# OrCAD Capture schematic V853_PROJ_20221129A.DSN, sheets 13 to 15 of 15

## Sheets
13 12 CARD/USB: size A3; note: USB
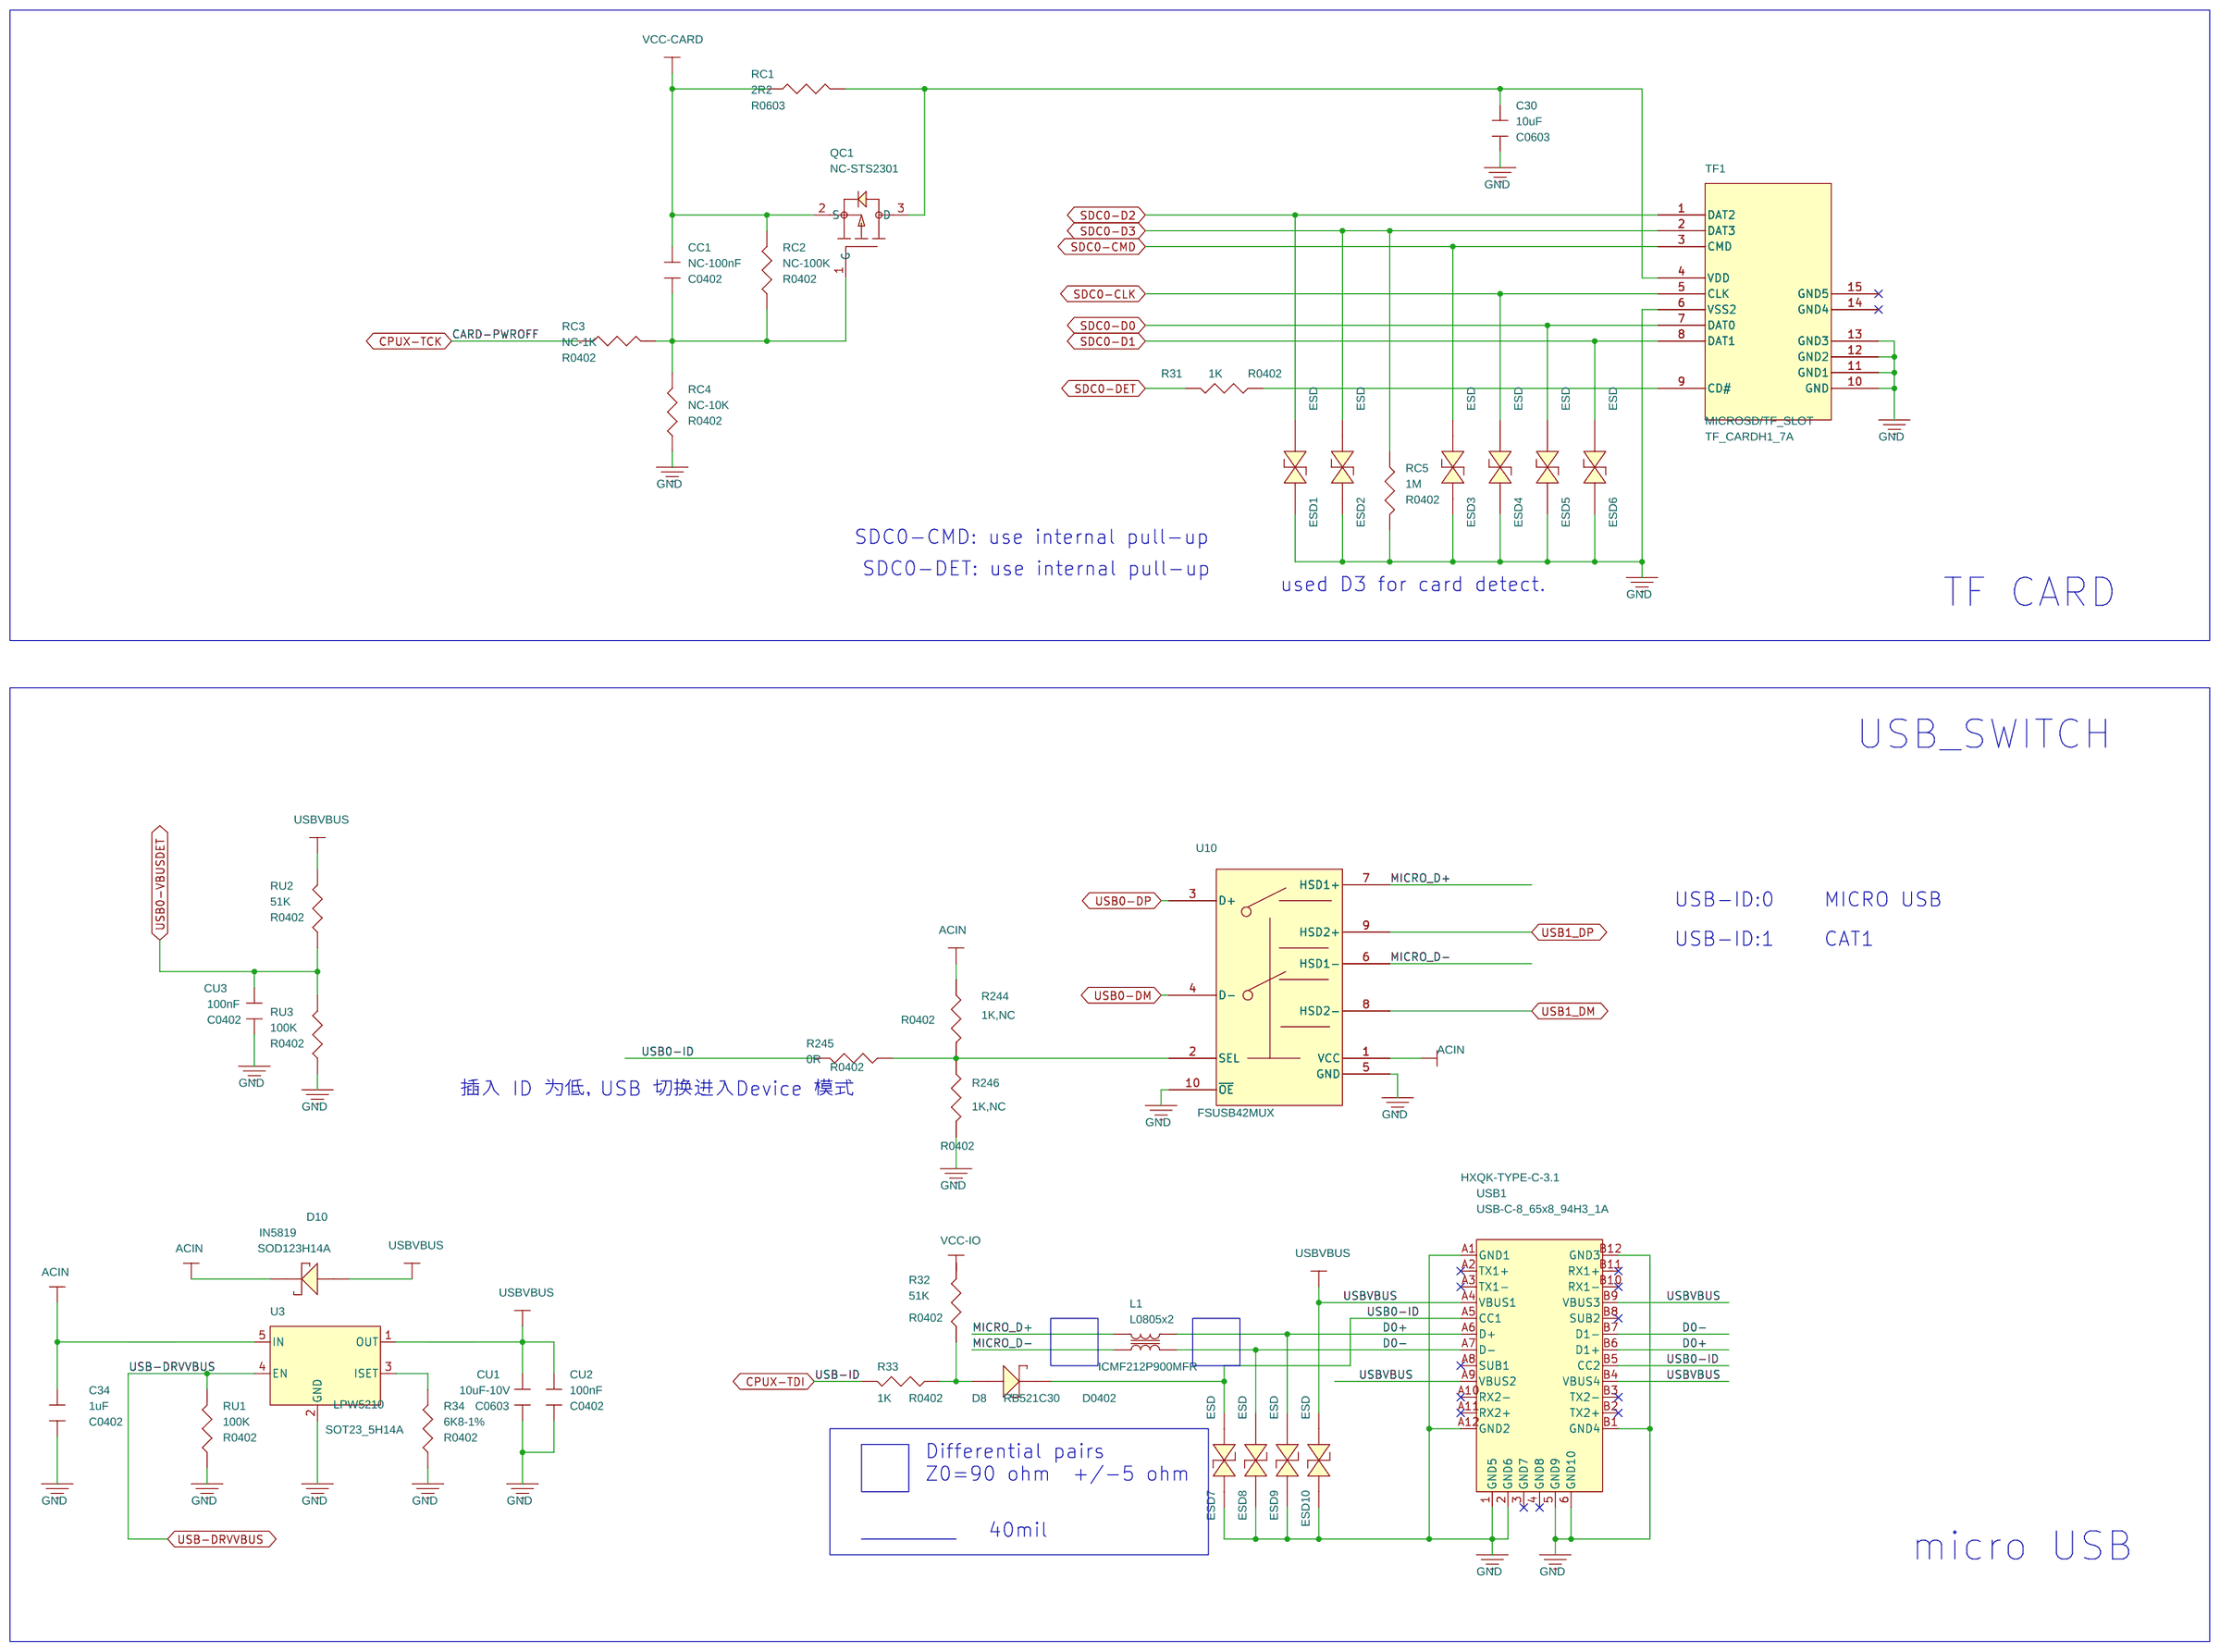
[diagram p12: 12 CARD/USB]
14 07 JTAG/DEBUG: size A3; note: JTAG/DEBUG
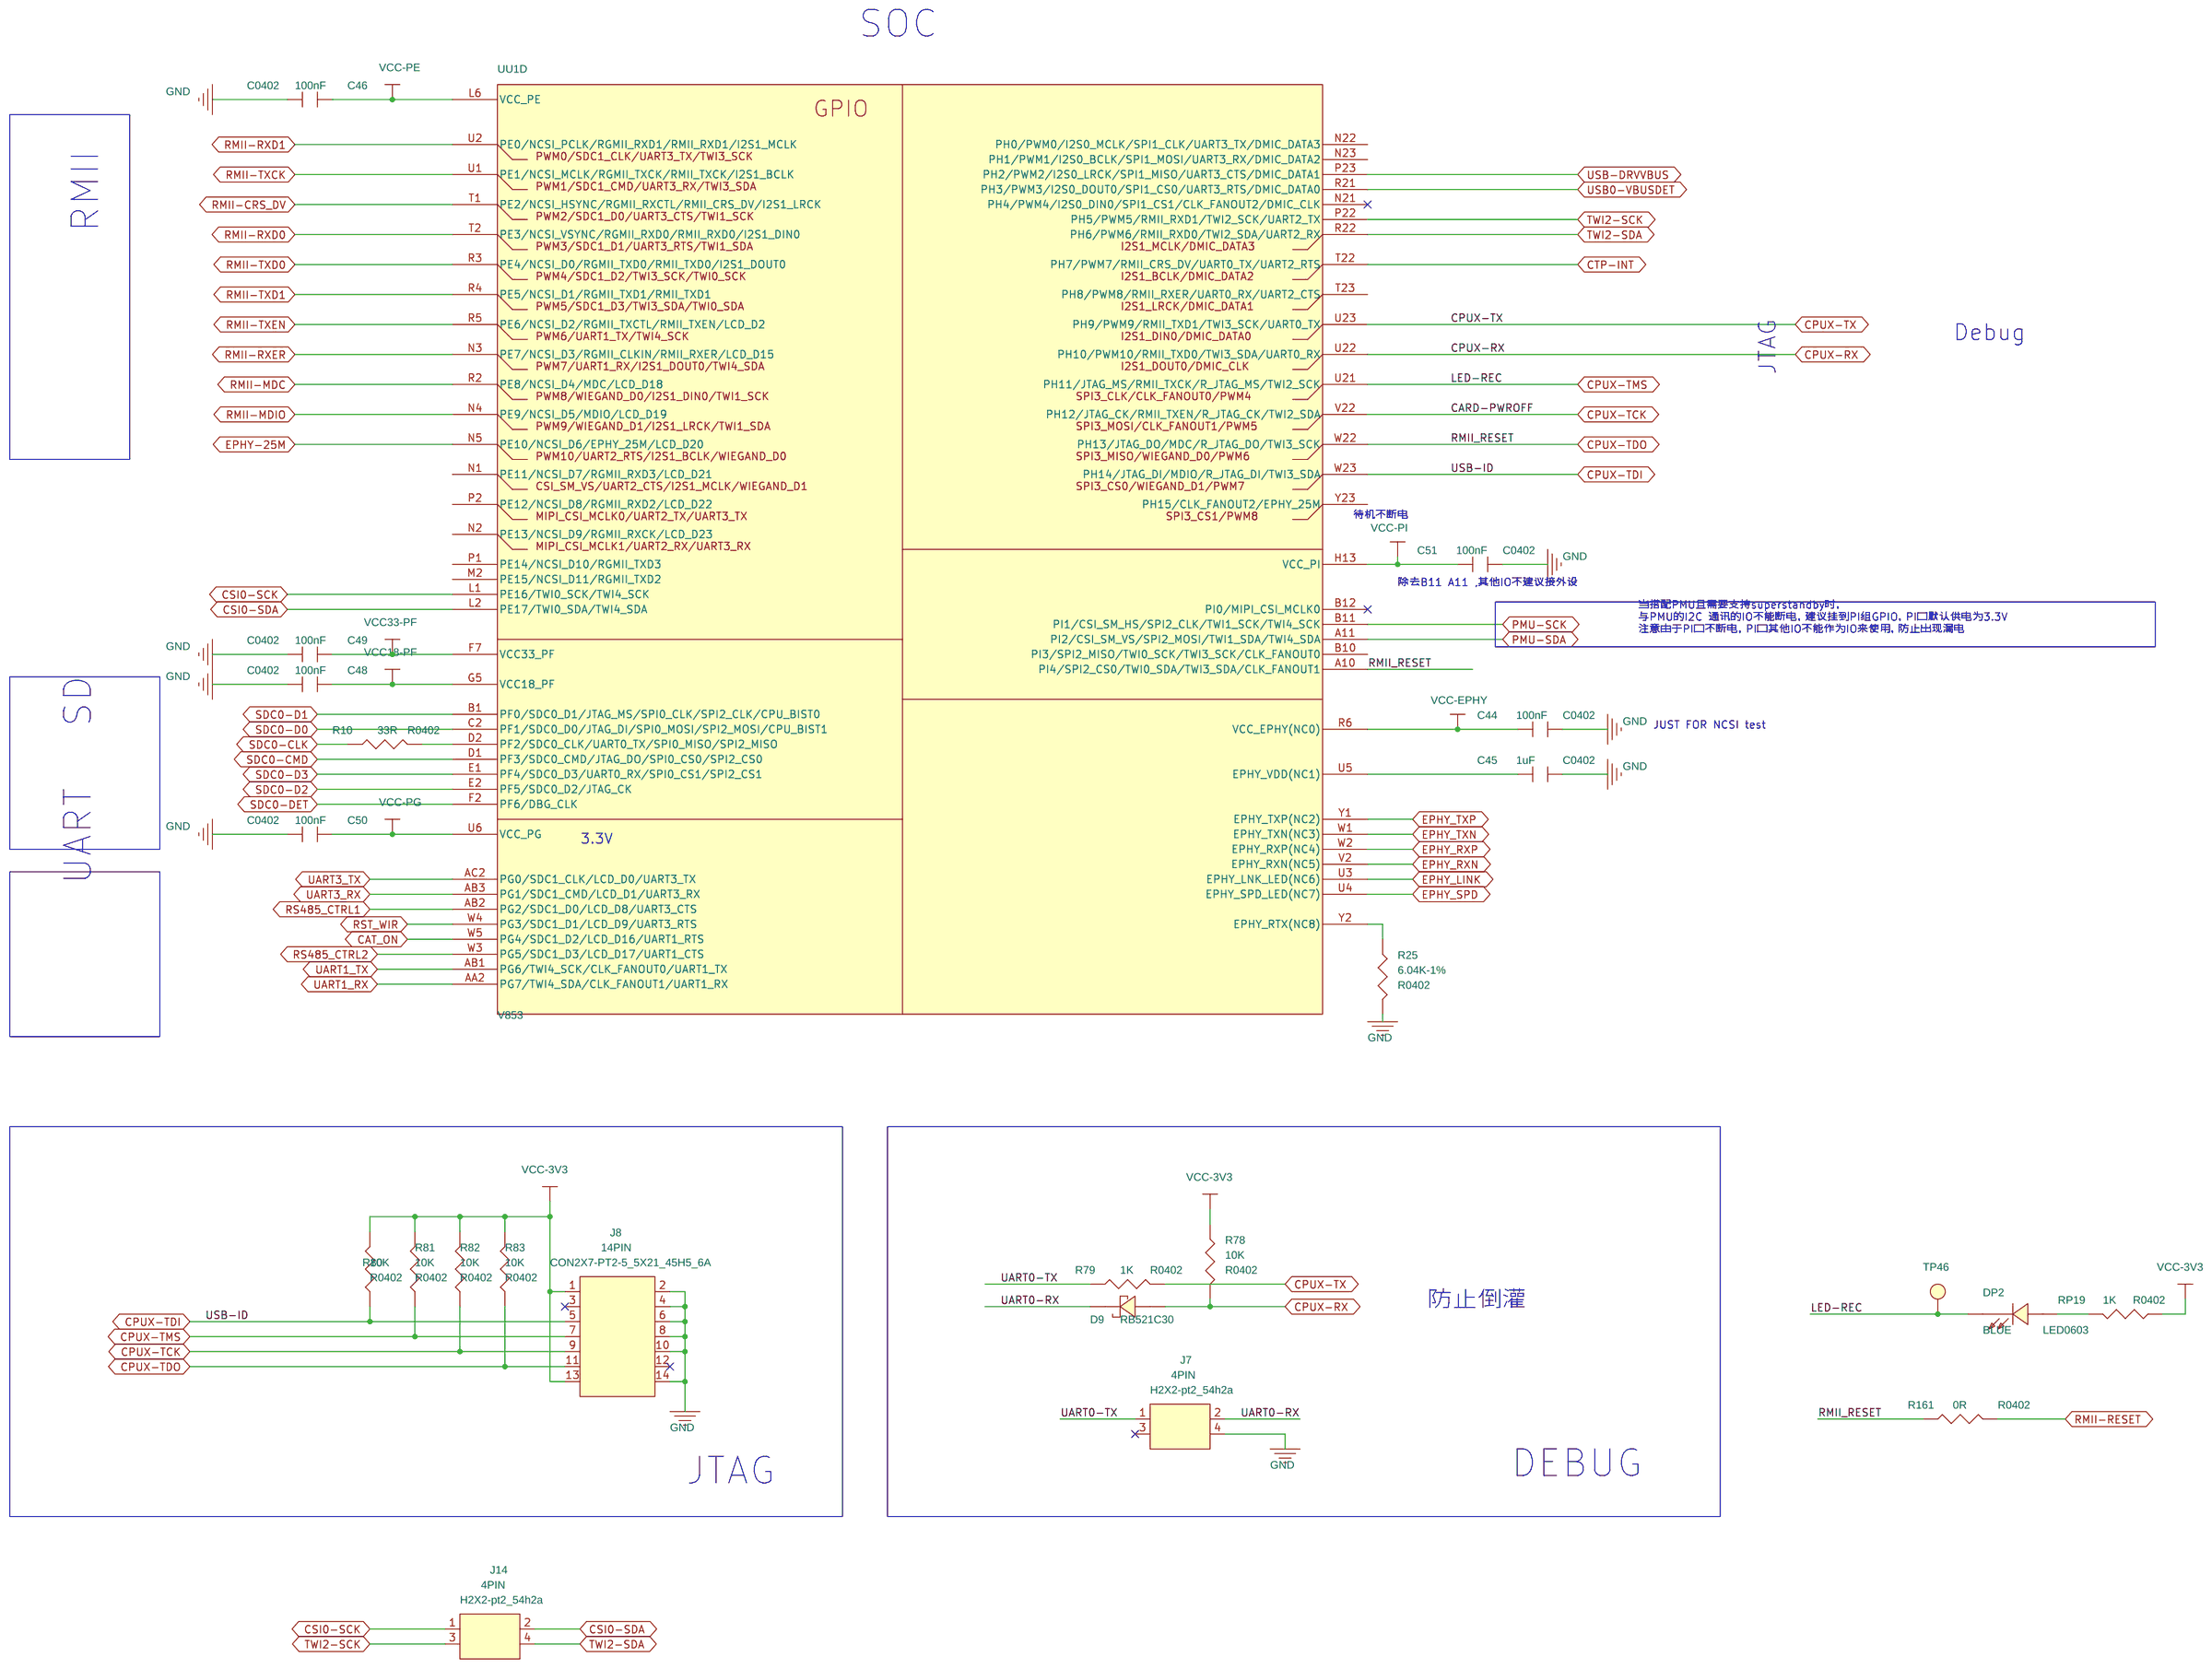
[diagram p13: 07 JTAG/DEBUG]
15 09 EMMC/BOOT-SEL: size A3; note: BootLoader
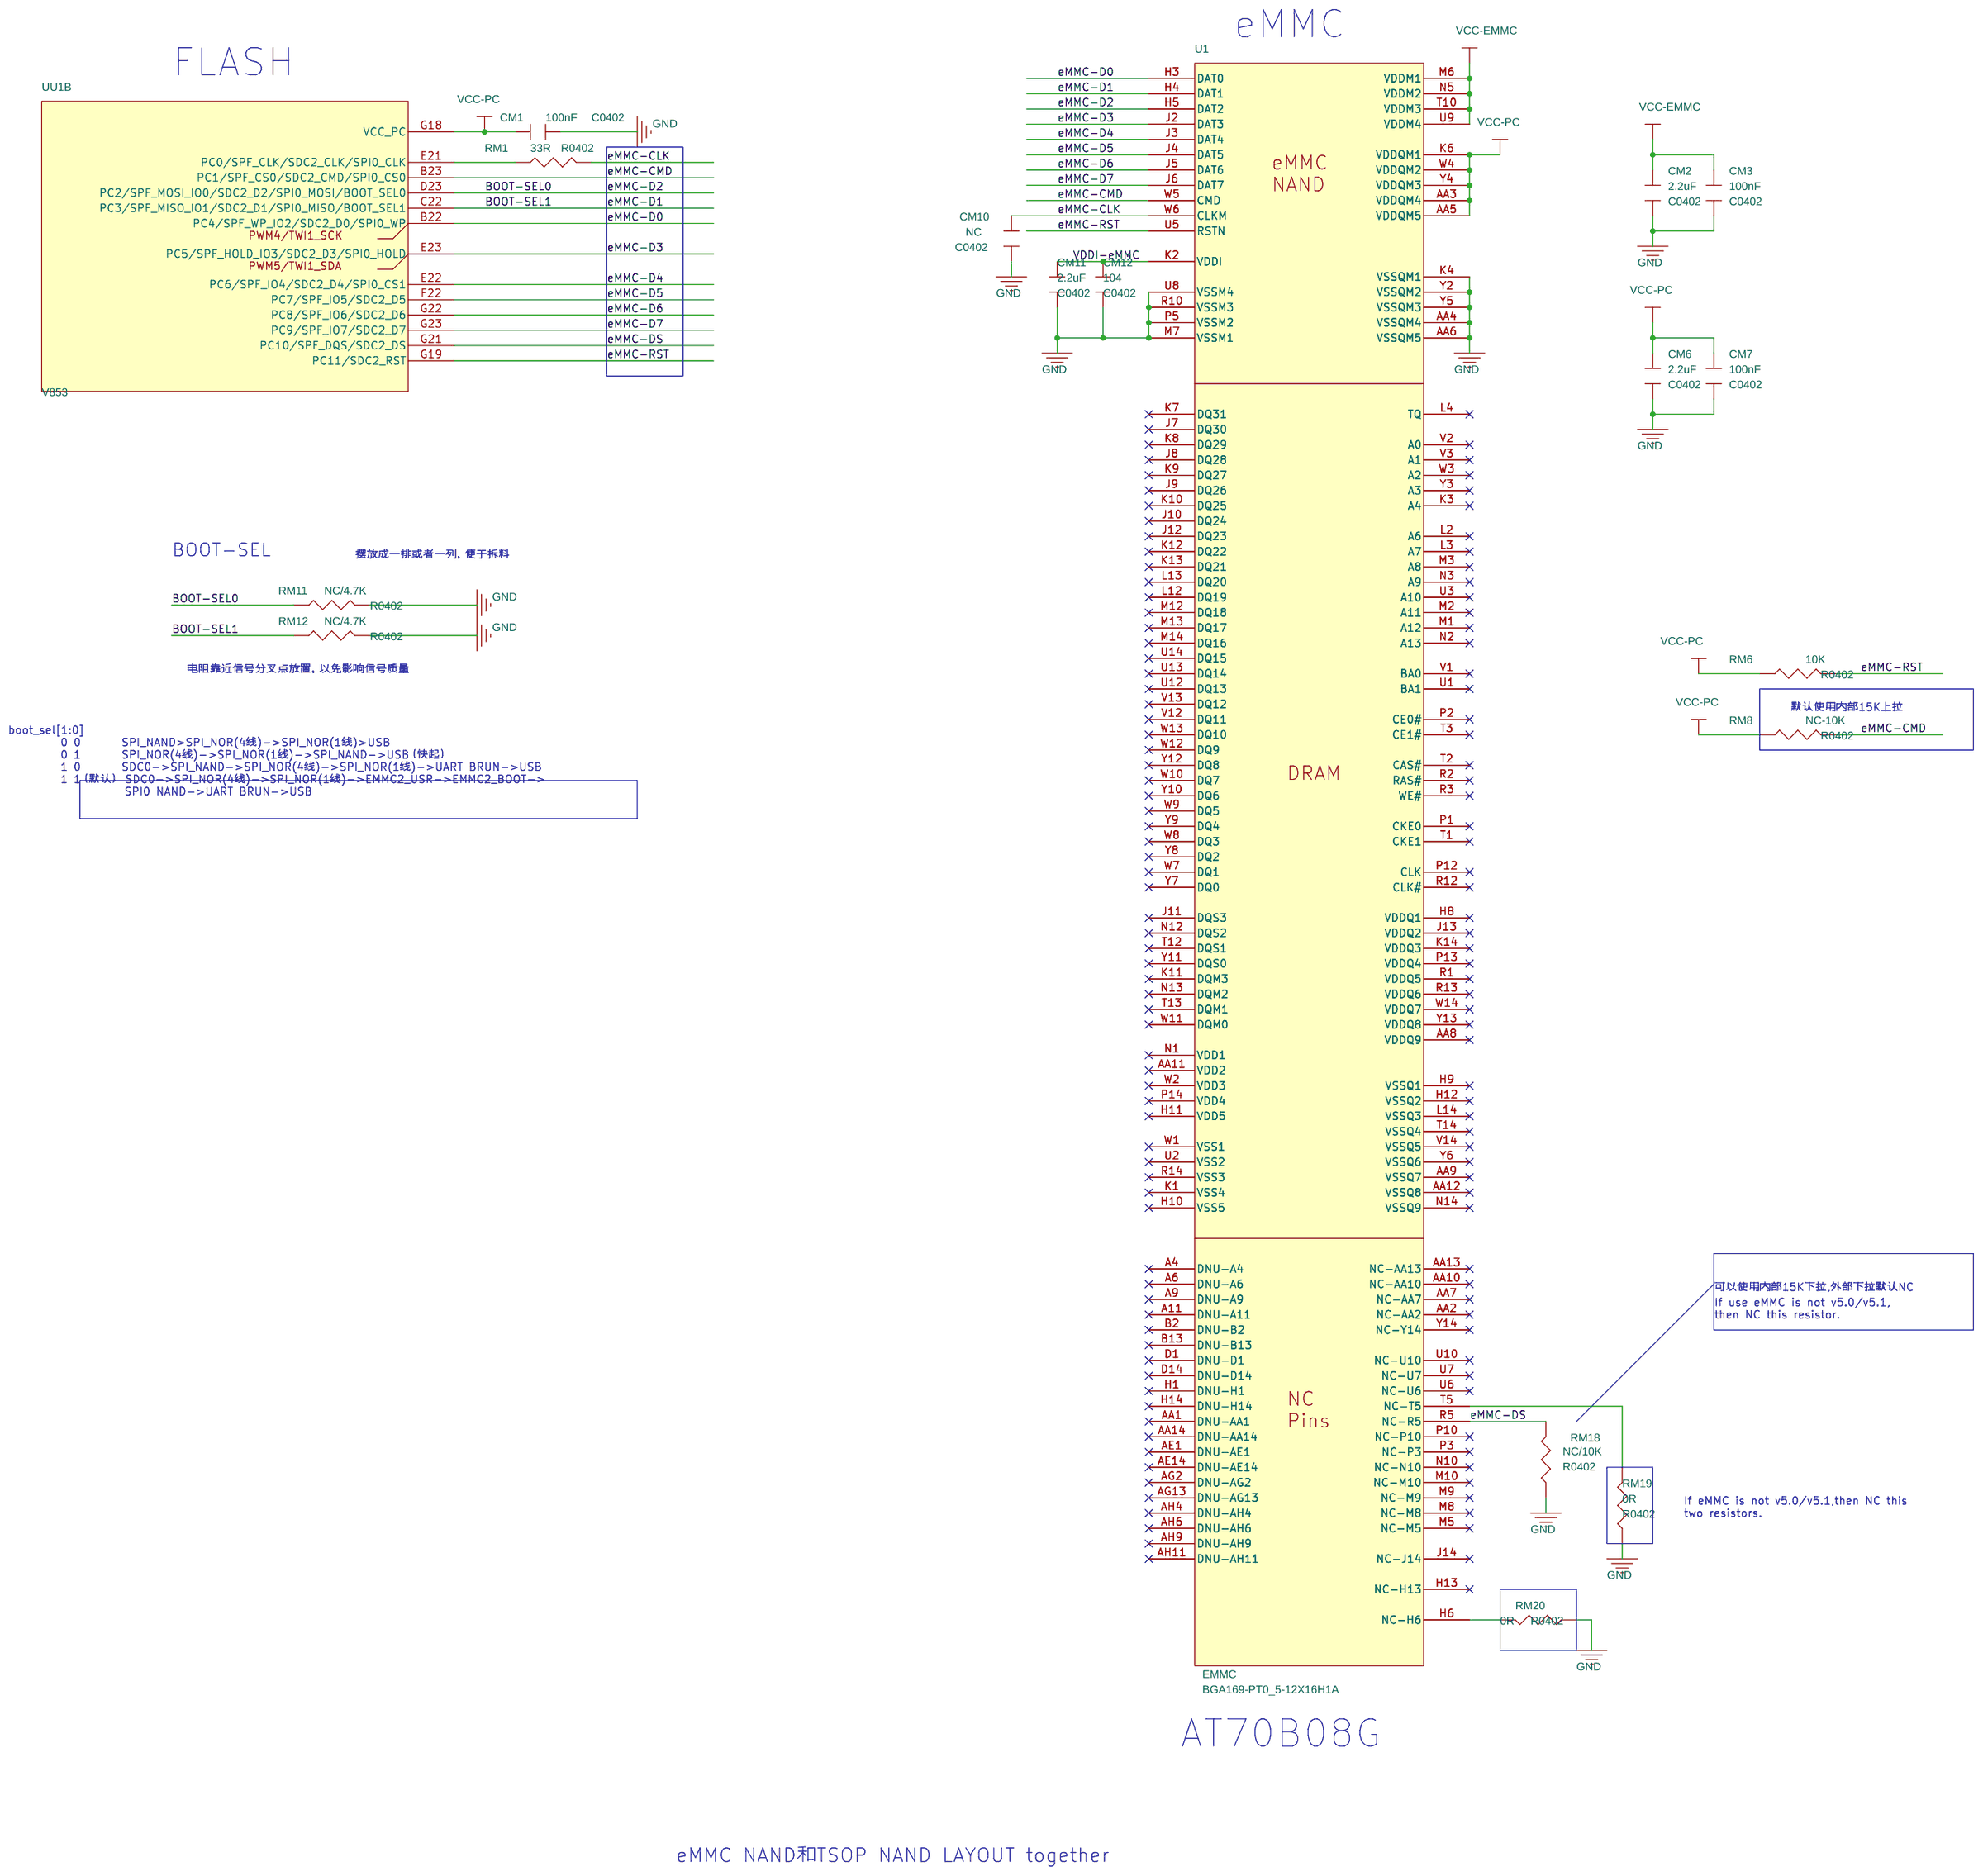
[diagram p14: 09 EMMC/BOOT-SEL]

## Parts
sheet 07 JTAG/DEBUG
C44  100nF  [C0402]
C45  1uF  [C0402]
C46  100nF  [C0402]
C48  100nF  [C0402]
C49  100nF  [C0402]
C50  100nF  [C0402]
C51  100nF  [C0402]
D9  RB521C30  [D0402]
DP2  BLUE  [LED0603]
J7  4PIN  [H2X2-pt2_54h2a]
J8  14PIN  [CON2X7-PT2-5_5X21_45H5_6A]
J14  4PIN  [H2X2-pt2_54h2a]
R10  33R  [R0402]
R25  6.04K-1%  [R0402]
R78  10K  [R0402]
R79  1K  [R0402]
R80  10K  [R0402]
R81  10K  [R0402]
R82  10K  [R0402]
R83  10K  [R0402]
R161  0R  [R0402]
RP19  1K  [R0402]
TP46  NC  [TP40_SMD]
UU1  V853  [bga318-V853-pT0_5-12X12h1_2a]  (sections A,B,C,D,E,F,G,H)
sheet 09 EMMC/BOOT-SEL
CM1  100nF  [C0402]
CM2  2.2uF  [C0402]
CM3  100nF  [C0402]
CM6  2.2uF  [C0402]
CM7  100nF  [C0402]
CM10  NC  [C0402]
CM11  2.2uF  [C0402]
CM12  104  [C0402]
RM1  33R  [R0402]
RM6  10K  [R0402]
RM8  NC-10K  [R0402]
RM11  NC/4.7K  [R0402]
RM12  NC/4.7K  [R0402]
RM18  NC/10K  [R0402]
RM19  0R  [R0402]
RM20  0R  [R0402]
U1  EMMC  [BGA169-PT0_5-12X16H1A]
sheet 12 CARD/USB
C30  10uF  [C0603]
C34  1uF  [C0402]
CC1  NC-100nF  [C0402]
CU1  10uF-10V  [C0603]
CU2  100nF  [C0402]
CU3  100nF  [C0402]
D8  RB521C30  [D0402]
D10  IN5819  [SOD123H14A]
ESD1  ESD  [R0402]
ESD2  ESD  [R0402]
ESD3  ESD  [R0402]
ESD4  ESD  [R0402]
ESD5  ESD  [R0402]
ESD6  ESD  [R0402]
ESD7  ESD  [R0402]
ESD8  ESD  [R0402]
ESD9  ESD  [R0402]
ESD10  ESD  [R0402]
L1  ICMF212P900MFR  [L0805x2]
QC1  NC-STS2301  [SOT-23]
R31  1K  [R0402]
R32  51K  [R0402]
R33  1K  [R0402]
R34  6K8-1%  [R0402]
R244  1K,NC  [R0402]
R245  0R  [R0402]
R246  1K,NC  [R0402]
RC1  2R2  [R0603]
RC2  NC-100K  [R0402]
RC3  NC-1K  [R0402]
RC4  NC-10K  [R0402]
RC5  1M  [R0402]
RU1  100K  [R0402]
RU2  51K  [R0402]
RU3  100K  [R0402]
TF1  MICROSD/TF_SLOT  [TF_CARDH1_7A]
U3  LPW5210  [SOT23_5H14A]
U10  FSUSB42MUX  [msop_10_0p5_3x3]
USB1  HXQK-TYPE-C-3.1  [USB-C-8_65x8_94H3_1A]

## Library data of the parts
C44 C45 C51 = C-C0402: PAGE: 2; ROOM: CPU
C46 C48-C50 CC1 CM2 CM3 CM6 CM7 CU2 CU3 = C-C0402
D9 = DIODE_SCHOTTKY: Schottky Barrier Diode/SCHOTTKY BARRIER DIODE 200MA; COMPONENT_WEIGHT: 60; PART NUMBER: RB520S-30/LRB520S-30T1; PART_NUMBER: RB521S-30; SPREADWIN PN: D2000041A/D2000041B; Vendor: CHANGJIANG/LRC; XT PN: D2000041A/D2000041B; YK Description: Schottky Barrier Diodes; YK PN: YK0015100064; YK Part number: RB520S30-2/TR; YK VENDER: WILL
DP2 = LED-0805: PAGE: 1
J7 J14 = FPC10-PT05A_1_v2
J8 = FPC10-PT05A_0
R10 R161 RC1-RC5 RM6 RM8 RM11 RM12 RM18 RU1-RU3 = R-R0402-5%
R25 = R-R0402-1%
R78 R79 = R1_0805: ROOM: DRAM
R31-R33 R80-R83 R244-R246 = R
RP19 = R-R0603-5%
TP46 = T_POINT_R
UU1 = V853_0621
CM1 = C-C0402: PAGE: 2
CM10 CM12 = C-C0402-X5R_0
CM11 = C-C0603-X5R_1: Parameter: C0603-X5R
RM1 = R-R0402-5%: mypage: 08
RM19 RM20 = R: mypage: 08
U1 = MCP-BGA169_5
C30 C34 = CAPACITOR
CU1 = C-C0603
D8 = DIODE_SCHOTTKY_0: RoHS 1.0 Ampere Schottky Barrier Rectifiers  SOD-123; Page: 7; ROOM: PMU
D10 = DIODE_SCHOTTKY_0
ESD1-ESD6 = ESD9B5VL
ESD7-ESD10 = 1_1.5KE100A: 1ST PART DESCRIPTION: WILL ESD9B5V Bidirection ESD Protection; Page: 11
L1 = INDUCTORx_0
QC1 = PMOS-STS2301
R34 = R: Page: 9
TF1 = SDMMC_SLOT_0
U3 = RT9266PE_0: Page: 9
U10 = FSUSB42MUX
USB1 = USB_MINI_SOCKET_1

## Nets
GND: C30.1 C34.1 C44.2 C45.2 C46.2 C48.2 C49.2 C50.2 C51.2 CM1.1 CM2.1 CM3.1 CM6.1 CM7.1 CM10.2 CM11.2 CM12.2 CU1.1 CU2.1 CU3.1 ESD1.1(ANODE) ESD2.1(ANODE) ESD3.1(ANODE) ESD4.1(ANODE) ESD5.1(ANODE) ESD6.1(ANODE) ESD7.2(CATHODE) ESD8.2(CATHODE) ESD9.2(CATHODE) ESD10.2(CATHODE) J7.4 J8.2 J8.4 J8.6 J8.8 J8.10 J8.14 R25.2 R34.1 R246.2 RC4.1 RC5.2 RM11.2 RM12.2 RM18.1 RM19.1 RM20.1 RU1.1 RU3.1 TF1.6(VSS2) TF1.10(GND) TF1.11(GND1) TF1.12(GND2) TF1.13(GND3) U1.AA4(VSSQM4) U1.AA6(VSSQM5) U1.K4(VSSQM1) U1.M7(VSSM1) U1.P5(VSSM2) U1.R10(VSSM3) U1.U8(VSSM4) U1.Y2(VSSQM2) U1.Y5(VSSQM3) U3.2(GND) U10.5(GND) U10.10(~{OE}) USB1.1(GND5) USB1.2(GND6) USB1.5(GND9) USB1.6(GND10) USB1.A1(GND1) USB1.A12(GND2) USB1.B1(GND4) USB1.B12(GND3) ; also on sheet 5 6 7 8 9 10 11 12
VCC18-PF: C48.1 UU1.G5(VCC18_PF) ; also on sheet 5
VCC33-PF: C49.1 UU1.F7(VCC33_PF) ; also on sheet 5
VCC-3V3: J8.1 J8.13 R78.1 R80.2 R81.2 R82.2 R83.2 RP19.1 ; also on sheet 5 8
VCC-CARD: CC1.2 QC1.2(S) RC1.1 RC2.2 ; also on sheet 5
VCC-EMMC: CM2.2 CM3.2 U1.M6(VDDM1) U1.N5(VDDM2) U1.T10(VDDM3) U1.U9(VDDM4) ; also on sheet 5
VCC-EPHY: C44.1 UU1.R6(VCC_EPHY(NC0)) ; also on sheet 5 11
VCC-IO: R32.2 ; also on sheet 5 6 8
VCC-PC: CM1.2 CM6.2 CM7.2 RM6.1 RM8.1 U1.AA3(VDDQM4) U1.AA5(VDDQM5) U1.K6(VDDQM1) U1.W4(VDDQM2) U1.Y4(VDDQM3) UU1.G18(VCC_PC) ; also on sheet 5
VCC-PE: C46.1 UU1.L6(VCC_PE) ; also on sheet 5
VCC-PG: C50.1 UU1.U6(VCC_PG) ; also on sheet 5
VCC-PI: C51.1 UU1.H13(VCC_PI) ; also on sheet 5
VDDI-eMMC: CM11.1 CM12.1 U1.K2(VDDI)
ACIN: C34.2 D10.2 R244.1 U3.5(IN) U10.1(VCC) ; also on sheet 5 10 12
BOOT-SEL0: RM11.1 U1.H5(DAT2) UU1.D23(PC2/SPF_MOSI_IO0/SDC2_D2/SPI0_MOSI/BOOT_SEL0)
BOOT-SEL1: RM12.1 U1.H4(DAT1) UU1.C22(PC3/SPF_MISO_IO1/SDC2_D1/SPI0_MISO/BOOT_SEL1)
CAT_ON: UU1.W5(PG4/SDC1_D2/LCD_D16/UART1_RTS) ; also on sheet 12
CPUX-RX: D9.1(ANODE) R78.2 UU1.U22(PH10/PWM10/RMII_TXD0/TWI3_SDA/UART0_RX)
CPUX-TCK: J8.9 R82.1 RC3.1 UU1.V22(PH12/JTAG_CK/RMII_TXEN/R_JTAG_CK/TWI2_SDA)
CPUX-TDI: J8.5 R33.2 R80.1 UU1.W23(PH14/JTAG_DI/MDIO/R_JTAG_DI/TWI3_SDA)
CPUX-TDO: J8.11 R83.1 R161.1 UU1.A10(PI4/SPI2_CS0/TWI0_SDA/TWI3_SDA/CLK_FANOUT1) UU1.W22(PH13/JTAG_DO/MDC/R_JTAG_DO/TWI3_SCK)
CPUX-TMS: DP2.2(CATHODE) J8.7 R81.1 TP46.1(TP) UU1.U21(PH11/JTAG_MS/RMII_TXCK/R_JTAG_MS/TWI2_SCK)
CPUX-TX: R79.2 UU1.U23(PH9/PWM9/RMII_TXD1/TWI3_SCK/UART0_TX)
CSI0-SCK: J14.1 UU1.L1(PE16/TWI0_SCK/TWI4_SCK)
CSI0-SDA: J14.2 UU1.L2(PE17/TWI0_SDA/TWI4_SDA)
CTP-INT: UU1.T22(PH7/PWM7/RMII_CRS_DV/UART0_TX/UART2_RTS) ; also on sheet 8
D0+: ESD9.1(ANODE) L1.4 USB1.A6(D+) USB1.B6(D1+)
D0-: ESD8.1(ANODE) L1.3 USB1.A7(D-) USB1.B7(D1-)
eMMC-CLK: CM10.1 RM1.2 U1.W6(CLKM)
eMMC-CMD: RM8.2 U1.W5(CMD) UU1.B23(PC1/SPF_CS0/SDC2_CMD/SPI0_CS0)
eMMC-D0: U1.H3(DAT0) UU1.B22(PC4/SPF_WP_IO2/SDC2_D0/SPI0_WP)
eMMC-D3: U1.J2(DAT3) UU1.E23(PC5/SPF_HOLD_IO3/SDC2_D3/SPI0_HOLD)
eMMC-D4: U1.J3(DAT4) UU1.E22(PC6/SPF_IO4/SDC2_D4/SPI0_CS1)
eMMC-D5: U1.J4(DAT5) UU1.F22(PC7/SPF_IO5/SDC2_D5)
eMMC-D6: U1.J5(DAT6) UU1.G22(PC8/SPF_IO6/SDC2_D6)
eMMC-D7: U1.J6(DAT7) UU1.G23(PC9/SPF_IO7/SDC2_D7)
eMMC-DS: RM18.2 U1.R5(NC-R5) UU1.G21(PC10/SPF_DQS/SDC2_DS)
eMMC-RST: RM6.2 U1.U5(RSTN) UU1.G19(PC11/SDC2_RST)
EPHY-25M: UU1.N5(PE10/NCSI_D6/EPHY_25M/LCD_D20) ; also on sheet 11
EPHY_LINK: UU1.U3(EPHY_LNK_LED(NC6)) ; also on sheet 11
EPHY_RXN: UU1.V2(EPHY_RXN(NC5)) ; also on sheet 11
EPHY_RXP: UU1.W2(EPHY_RXP(NC4)) ; also on sheet 11
EPHY_SPD: UU1.U4(EPHY_SPD_LED(NC7)) ; also on sheet 11
EPHY_TXN: UU1.W1(EPHY_TXN(NC3)) ; also on sheet 11
EPHY_TXP: UU1.Y1(EPHY_TXP(NC2)) ; also on sheet 11
MICRO_D+: L1.2 U10.7(HSD1+)
MICRO_D-: L1.1 U10.6(HSD1-)
PMU-SCK: UU1.B11(PI1/CSI_SM_HS/SPI2_CLK/TWI1_SCK/TWI4_SCK) ; also on sheet 5
PMU-SDA: UU1.A11(PI2/CSI_SM_VS/SPI2_MOSI/TWI1_SDA/TWI4_SDA) ; also on sheet 5
RMII-CRS_DV: UU1.T1(PE2/NCSI_HSYNC/RGMII_RXCTL/RMII_CRS_DV/I2S1_LRCK) ; also on sheet 11
RMII-MDC: UU1.R2(PE8/NCSI_D4/MDC/LCD_D18) ; also on sheet 11
RMII-MDIO: UU1.N4(PE9/NCSI_D5/MDIO/LCD_D19) ; also on sheet 11
RMII-RESET: R161.2 ; also on sheet 11
RMII-RXD0: UU1.T2(PE3/NCSI_VSYNC/RGMII_RXD0/RMII_RXD0/I2S1_DIN0) ; also on sheet 11
RMII-RXD1: UU1.U2(PE0/NCSI_PCLK/RGMII_RXD1/RMII_RXD1/I2S1_MCLK) ; also on sheet 11
RMII-RXER: UU1.N3(PE7/NCSI_D3/RGMII_CLKIN/RMII_RXER/LCD_D15) ; also on sheet 11
RMII-TXCK: UU1.U1(PE1/NCSI_MCLK/RGMII_TXCK/RMII_TXCK/I2S1_BCLK) ; also on sheet 11
RMII-TXD0: UU1.R3(PE4/NCSI_D0/RGMII_TXD0/RMII_TXD0/I2S1_DOUT0) ; also on sheet 11
RMII-TXD1: UU1.R4(PE5/NCSI_D1/RGMII_TXD1/RMII_TXD1) ; also on sheet 11
RMII-TXEN: UU1.R5(PE6/NCSI_D2/RGMII_TXCTL/RMII_TXEN/LCD_D2) ; also on sheet 11
RS485_CTRL1: UU1.AB2(PG2/SDC1_D0/LCD_D8/UART3_CTS) ; also on sheet 10
RS485_CTRL2: UU1.W3(PG5/SDC1_D3/LCD_D17/UART1_CTS) ; also on sheet 10
RST_WIR: UU1.W4(PG3/SDC1_D1/LCD_D9/UART3_RTS) ; also on sheet 12
SDC0-CLK: ESD4.2(CATHODE) R10.1 TF1.5(CLK)
SDC0-CMD: ESD3.2(CATHODE) TF1.3(CMD) UU1.D1(PF3/SDC0_CMD/JTAG_DO/SPI0_CS0/SPI2_CS0)
SDC0-D0: ESD5.2(CATHODE) TF1.7(DAT0) UU1.C2(PF1/SDC0_D0/JTAG_DI/SPI0_MOSI/SPI2_MOSI/CPU_BIST1)
SDC0-D1: ESD6.2(CATHODE) TF1.8(DAT1) UU1.B1(PF0/SDC0_D1/JTAG_MS/SPI0_CLK/SPI2_CLK/CPU_BIST0)
SDC0-D2: ESD1.2(CATHODE) TF1.1(DAT2) UU1.E2(PF5/SDC0_D2/JTAG_CK)
SDC0-D3: ESD2.2(CATHODE) RC5.1 TF1.2(DAT3) UU1.E1(PF4/SDC0_D3/UART0_RX/SPI0_CS1/SPI2_CS1)
SDC0-DET: R31.2 UU1.F2(PF6/DBG_CLK)
TWI2-SCK: J14.3 UU1.P22(PH5/PWM5/RMII_RXD1/TWI2_SCK/UART2_TX)
TWI2-SDA: J14.4 UU1.R22(PH6/PWM6/RMII_RXD0/TWI2_SDA/UART2_RX)
UART0-RX: D9.2(CATHODE) J7.2
UART0-TX: J7.1 R79.1
UART1_RX: UU1.AA2(PG7/TWI4_SDA/CLK_FANOUT1/UART1_RX) ; also on sheet 10
UART1_TX: UU1.AB1(PG6/TWI4_SCK/CLK_FANOUT0/UART1_TX) ; also on sheet 10
UART3_RX: UU1.AB3(PG1/SDC1_CMD/LCD_D1/UART3_RX) ; also on sheet 10
UART3_TX: UU1.AC2(PG0/SDC1_CLK/LCD_D0/UART3_TX) ; also on sheet 10
USB0-DM: U10.4(D-) ; also on sheet 6
USB0-DP: U10.3(D+) ; also on sheet 6
USB0-ID: D8.2 ESD7.1(ANODE) R245.2 USB1.A5(CC1) USB1.B5(CC2)
USB0-VBUSDET: CU3.2 RU2.1 RU3.2 UU1.R21(PH3/PWM3/I2S0_DOUT0/SPI1_CS0/UART3_RTS/DMIC_DATA0)
USB1_DM: U10.8(HSD2-) ; also on sheet 12
USB1_DP: U10.9(HSD2+) ; also on sheet 12
USB-DRVVBUS: RU1.2 U3.4(EN) UU1.P23(PH2/PWM2/I2S0_LRCK/SPI1_MISO/UART3_CTS/DMIC_DATA1)
USBVBUS: CU1.2 CU2.2 D10.1 ESD10.1(ANODE) RU2.2 U3.1(OUT) USB1.A4(VBUS1) USB1.A9(VBUS2) USB1.B4(VBUS4) USB1.B9(VBUS3)
N19994654: RM1.1 UU1.E21(PC0/SPF_CLK/SDC2_CLK/SPI0_CLK)
N20043374: R10.2 UU1.D2(PF2/SDC0_CLK/UART0_TX/SPI0_MISO/SPI2_MISO)
N20316222: C45.1 UU1.U5(EPHY_VDD(NC1))
N20326782: R25.1 UU1.Y2(EPHY_RTX(NC8))
N20689650: RM20.2 U1.H6(NC-H6)
N20689652: RM19.2 U1.T5(NC-T5)
N20774021: C30.2 QC1.3(D) RC1.2 TF1.4(VDD)
N20774054: R31.1 TF1.9(CD#)
N20774199: CC1.1 QC1.1(G) RC2.1 RC3.2 RC4.2
N20777011: R34.2 U3.3(ISET)
N20861869: DP2.1(ANODE) RP19.2
N20927195: D8.1 R32.1 R33.1
N21399625: R244.2 R245.1 R246.1 U10.2(SEL)

Not connected (* = marked no-connect by the designer): J7 3*; J8 3* 12*; TF1 14(GND4)* 15(GND5)*; U1 A4(DNU-A4)* A6(DNU-A6)* A9(DNU-A9)* A11(DNU-A11)* AA1(DNU-AA1)* AA2(NC-AA2)* AA7(NC-AA7)* AA8(VDDQ9)* AA9(VSSQ7)* AA10(NC-AA10)* AA11(VDD2)* AA12(VSSQ8)* AA13(NC-AA13)* AA14(DNU-AA14)* AE1(DNU-AE1)* AE14(DNU-AE14)* AG2(DNU-AG2)* AG13(DNU-AG13)* AH4(DNU-AH4)* AH6(DNU-AH6)* AH9(DNU-AH9)* AH11(DNU-AH11)* B2(DNU-B2)* B13(DNU-B13)* D1(DNU-D1)* D14(DNU-D14)* H1(DNU-H1)* H8(VDDQ1)* H9(VSSQ1)* H10(VSS5)* H11(VDD5)* H12(VSSQ2)* H13(NC-H13)* H14(DNU-H14)* J7(DQ30)* J8(DQ28)* J9(DQ26)* J10(DQ24)* J11(DQS3)* J12(DQ23)* J13(VDDQ2)* J14(NC-J14)* K1(VSS4)* K3(A4)* K7(DQ31)* K8(DQ29)* K9(DQ27)* K10(DQ25)* K11(DQM3)* K12(DQ22)* K13(DQ21)* K14(VDDQ3)* L2(A6)* L3(A7)* L4(TQ)* L12(DQ19)* L13(DQ20)* L14(VSSQ3)* M1(A12)* M2(A11)* M3(A8)* M5(NC-M5)* M8(NC-M8)* M9(NC-M9)* M10(NC-M10)* M12(DQ18)* M13(DQ17)* M14(DQ16)* N1(VDD1)* N2(A13)* N3(A9)* N10(NC-N10)* N12(DQS2)* N13(DQM2)* N14(VSSQ9)* P1(CKE0)* P2(CE0#)* P3(NC-P3)* P10(NC-P10)* P12(CLK)* P13(VDDQ4)* P14(VDD4)* R1(VDDQ5)* R2(RAS#)* R3(WE#)* R12(CLK#)* R13(VDDQ6)* R14(VSS3)* T1(CKE1)* T2(CAS#)* T3(CE1#)* T12(DQS1)* T13(DQM1)* T14(VSSQ4)* U1(BA1)* U2(VSS2)* U3(A10)* U6(NC-U6)* U7(NC-U7)* U10(NC-U10)* U12(DQ13)* U13(DQ14)* U14(DQ15)* V1(BA0)* V2(A0)* V3(A1)* V12(DQ11)* V13(DQ12)* V14(VSSQ5)* W1(VSS1)* W2(VDD3)* W3(A2)* W7(DQ1)* W8(DQ3)* W9(DQ5)* W10(DQ7)* W11(DQM0)* W12(DQ9)* W13(DQ10)* W14(VDDQ7)* Y3(A3)* Y6(VSSQ6)* Y7(DQ0)* Y8(DQ2)* Y9(DQ4)* Y10(DQ6)* Y11(DQS0)* Y12(DQ8)* Y13(VDDQ8)* Y14(NC-Y14)*; USB1 3(GND7)* 4(GND8)* A2(TX1+)* A3(TX1-)* A8(SUB1)* A10(RX2-)* A11(RX2+)* B2(TX2+)* B3(TX2-)* B8(SUB2)* B10(RX1-)* B11(RX1+)*; UU1 B10(PI3/SPI2_MISO/TWI0_SCK/TWI3_SCK/CLK_FANOUT0) B12(PI0/MIPI_CSI_MCLK0)* M2(PE15/NCSI_D11/RGMII_TXD2) N1(PE11/NCSI_D7/RGMII_RXD3/LCD_D21) N2(PE13/NCSI_D9/RGMII_RXCK/LCD_D23) N21(PH4/PWM4/I2S0_DIN0/SPI1_CS1/CLK_FANOUT2/DMIC_CLK)* N22(PH0/PWM0/I2S0_MCLK/SPI1_CLK/UART3_TX/DMIC_DATA3) N23(PH1/PWM1/I2S0_BCLK/SPI1_MOSI/UART3_RX/DMIC_DATA2) P1(PE14/NCSI_D10/RGMII_TXD3) P2(PE12/NCSI_D8/RGMII_RXD2/LCD_D22) T23(PH8/PWM8/RMII_RXER/UART0_RX/UART2_CTS) Y23(PH15/CLK_FANOUT2/EPHY_25M)

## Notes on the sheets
sheet 13
- SDC0-CMD: use internal pull-up
- SDC0-DET: use internal pull-up
- used D3 for card detect.
- TF CARD
- USB_SWITCH
- USB-ID:0
- MICRO USB
- USB-ID:1
- CAT1
- 插入 ID 为低，USB 切换进入Device 模式
- Differential pairs
  Z0=90 ohm  +/-5 ohm
- 40mil
- micro USB
sheet 14
- SOC
- RMII
- Debug
- JTAG
- 待机不断电
- 除去B11 A11 ,其他IO不建议接外设
- 当搭配PMU且需要支持superstandby时，
  与PMU的I2C 通讯的IO不能断电，建议挂到PI组GPIO，PI口默认供电为3.3V
  注意由于PI口不断电，PI口其他IO不能作为IO来使用，防止出现漏电
- SD
- JUST FOR NCSI test
- 3.3V
- UART
- 防止倒灌
- JTAG
- DEBUG
sheet 15
- eMMC
- FLASH
- BOOT-SEL
- 摆放成一排或者一列，便于拆料
- 电阻靠近信号分叉点放置，以免影响信号质量
- 默认使用内部15K上拉
- boot_sel[1:0]
             0 0       SPI_NAND>SPI_NOR(4线)->SPI_NOR(1线)>USB
             0 1       SPI_NOR(4线)->SPI_NOR(1线)->SPI_NAND->USB（快起）
             1 0       SDC0->SPI_NAND->SPI_NOR(4线)->SPI_NOR(1线)->UART BRUN->USB
             1 1（默认） SDC0->SPI_NOR(4线)->SPI_NOR(1线)->EMMC2_USR->EMMC2_BOOT->
                        SPI0 NAND->UART BRUN->USB
- 可以使用内部15K下拉,外部下拉默认NC
- If use eMMC is not v5.0/v5.1,
  then NC this resistor.
- If eMMC is not v5.0/v5.1,then NC this
  two resistors.
- AT70B08G
- eMMC NAND和TSOP NAND LAYOUT together
